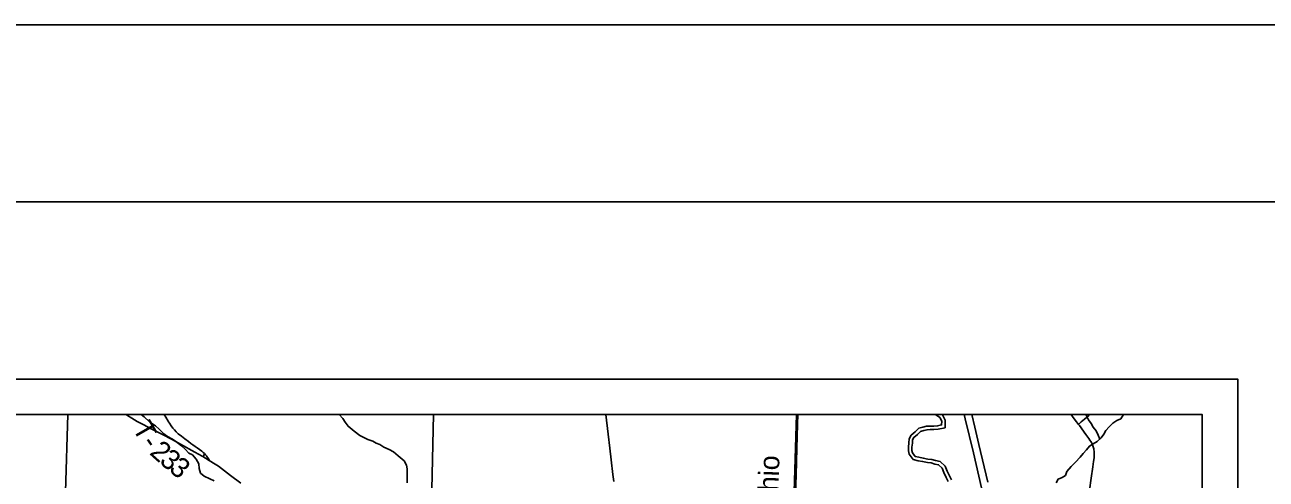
# Model space of a CAD drawing. Extents: x 0 to 34, y 0 to 22.
# Drawn here: x 26.994 to 30.497, y 20.718 to 22 of the extents above; entities that cross this region are included whole.
import ezdxf

# ---------------------------------------------------------------- set-up
doc = ezdxf.new("R2010")
doc.units = 0
for name, color, linetype in [('GM_X_Corporation', 7, 'Continuous'), ('GM_X_County_Road', 7, 'Continuous'), ('GM_X_Interstate_Route', 7, 'Continuous'), ('GM_X_Major_River', 7, 'Continuous'), ('GM_X_Minor_River', 7, 'Continuous'), ('GM_X_Rail_Line', 7, 'Continuous'), ('GM_X_Rail_Line_Text', 7, 'Continuous'), ('GM_X_State_Route', 7, 'Continuous'), ('GM_X_Township_Road', 7, 'Continuous'), ('GM_X_Township_Road_Text', 7, 'Continuous'), ('SH_Border', 7, 'Continuous'), ('SH_Cut_Line', 7, 'Continuous'), ('SH_Data', 7, 'Continuous')]:
    doc.layers.add(name, color=color, linetype=linetype)

msp = doc.modelspace()

# ---------------------------------------------------------------- linework, layer by layer
at = {"layer": 'GM_X_Corporation'}
for points in [[(26.6535, 14.621), (27.01, 14.6164), (27.046, 14.6155), (27.043, 14.755), (27.052, 15.403), (27.0676, 16.5549), (27.0694, 16.6556), (27.0775, 16.888), (27.0944, 18.0731), (27.1039, 18.5696), (27.1064, 18.6537), (27.3971, 18.6436), (28.3421, 18.6121), (28.7772, 18.6028), (29.0074, 18.5935), (29.6561, 18.5791), (29.6772, 18.5786), (30.101, 18.5701), (30.3167, 18.565), (30.3167, 20.9), (23.5167, 20.9)], [(26.3378, 16.673), (27.0694, 16.6556), (27.0775, 16.888), (27.0944, 18.0731), (27.1039, 18.5696), (27.1064, 18.6537), (27.3971, 18.6436), (28.3421, 18.6121), (28.7772, 18.6028), (29.0074, 18.5935), (29.6561, 18.5791), (29.6772, 18.5786), (30.101, 18.5701), (30.3167, 18.565), (30.3167, 20.9), (25.1014, 20.9)]]:
    msp.add_lwpolyline(points, dxfattribs=at)
for points in [[(27.1148, 20.9), (26.1019, 20.9), (26.0969, 20.7089), (26.1216, 20.708), (27.1086, 20.6823)], [(28.1474, 20.9), (27.1148, 20.9), (27.1086, 20.6823), (27.14, 20.6818), (28.1412, 20.646)], [(29.1717, 20.9), (28.1474, 20.9), (28.1412, 20.646), (28.1583, 20.645), (29.1631, 20.6187)]]:
    msp.add_lwpolyline(points, close=True, dxfattribs=at)
at = {"layer": 'GM_X_County_Road'}
for points in [[(29.9671, 20.8723), (29.9619, 20.8793), (29.9525, 20.8917), (29.9464, 20.9)], [(29.998, 20.6871), (30.0029, 20.7203), (30.0078, 20.7522), (30.0099, 20.7676), (30.0111, 20.778), (30.0116, 20.7854), (30.0116, 20.7916), (30.0112, 20.7971), (30.0108, 20.8004), (30.0103, 20.8031), (30.0097, 20.8062), (30.009, 20.8085), (30.0079, 20.812), (30.0067, 20.815), (30.0056, 20.8176), (30.0037, 20.8211), (30.0018, 20.8242), (29.9994, 20.8278), (29.9965, 20.8323), (29.9882, 20.8439), (29.9697, 20.8688), (29.9671, 20.8723)]]:
    msp.add_lwpolyline(points, dxfattribs=at)
at = {"layer": 'GM_X_Interstate_Route'}
for points in [[(29.7763, 20.3387), (29.7722, 20.3591), (29.7621, 20.4065), (29.7537, 20.4429), (29.7354, 20.5196), (29.7175, 20.5946), (29.694, 20.6937), (29.6706, 20.7916), (29.6477, 20.8877), (29.6447, 20.9)], [(29.7116, 20.709), (29.6862, 20.8153), (29.6744, 20.8649), (29.6661, 20.9)]]:
    msp.add_lwpolyline(points, dxfattribs=at)
at = {"layer": 'GM_X_Major_River'}
for points in [[(29.5999, 20.7112), (29.5942, 20.7225), (29.5872, 20.7365), (29.5826, 20.749), (29.5723, 20.7583), (29.5617, 20.7605), (29.5514, 20.7634), (29.5409, 20.7648), (29.5272, 20.7677), (29.5151, 20.7699), (29.5011, 20.7731), (29.4892, 20.7878), (29.4876, 20.7976), (29.4872, 20.8082), (29.4889, 20.82), (29.4892, 20.8314), (29.4948, 20.8417), (29.5064, 20.8513), (29.5166, 20.8612), (29.5279, 20.8648), (29.5384, 20.8671), (29.5486, 20.8676), (29.5588, 20.8677), (29.5698, 20.8682), (29.5811, 20.8706), (29.5814, 20.8816), (29.5756, 20.8922), (29.5638, 20.9)], [(29.6087, 20.7156), (29.6029, 20.727), (29.5963, 20.7404), (29.591, 20.7546), (29.5769, 20.7674), (29.564, 20.77), (29.5535, 20.7731), (29.5425, 20.7745), (29.5291, 20.7774), (29.5171, 20.7795), (29.5066, 20.7819), (29.4985, 20.7919), (29.4974, 20.7986), (29.497, 20.8077), (29.4988, 20.8191), (29.499, 20.8288), (29.5025, 20.8353), (29.513, 20.8439), (29.5218, 20.8525), (29.5304, 20.8552), (29.5398, 20.8574), (29.5489, 20.8578), (29.5591, 20.8579), (29.571, 20.8584), (29.5907, 20.8626), (29.5913, 20.884), (29.5831, 20.899), (29.5816, 20.9)], [(29.6087, 20.7156), (29.6029, 20.727), (29.5963, 20.7404), (29.591, 20.7546), (29.5769, 20.7674), (29.564, 20.77), (29.5535, 20.7731), (29.5425, 20.7745), (29.5291, 20.7774), (29.5171, 20.7795), (29.5066, 20.7819), (29.4985, 20.7919), (29.4974, 20.7986), (29.497, 20.8077), (29.4988, 20.8191), (29.499, 20.8288), (29.5025, 20.8353), (29.513, 20.8439), (29.5218, 20.8525), (29.5304, 20.8552), (29.5398, 20.8574), (29.5489, 20.8578), (29.5591, 20.8579), (29.571, 20.8584), (29.5907, 20.8626), (29.5913, 20.884), (29.5831, 20.899), (29.5816, 20.9)]]:
    msp.add_lwpolyline(points, dxfattribs=at)
at = {"layer": 'GM_X_Minor_River'}
for points in [[(27.5283, 20.7133), (27.5162, 20.7189), (27.5002, 20.7259), (27.49, 20.7349), (27.4861, 20.7481), (27.4844, 20.7614), (27.4775, 20.7738), (27.4668, 20.7862), (27.4569, 20.791), (27.4463, 20.8019), (27.436, 20.812), (27.4192, 20.8251), (27.4082, 20.8318), (27.396, 20.8378), (27.3858, 20.8456), (27.3732, 20.8584), (27.3629, 20.8685), (27.3458, 20.8793), (27.3302, 20.8935), (27.322, 20.9)], [(28.0723, 20.7077), (28.0726, 20.7233), (28.0724, 20.7471), (28.0708, 20.7574), (28.0642, 20.7694), (28.0471, 20.784), (28.0341, 20.7949), (28.0216, 20.8012), (28.0072, 20.8082), (27.9958, 20.8153), (27.9855, 20.8197), (27.9757, 20.8253), (27.962, 20.8301), (27.9525, 20.8346), (27.9392, 20.8405), (27.9229, 20.8528), (27.9061, 20.867), (27.8977, 20.8783), (27.8908, 20.8885), (27.8812, 20.9)], [(29.9039, 20.7076), (29.9095, 20.7179), (29.9208, 20.7222), (29.9309, 20.7283), (29.9342, 20.7394), (29.9466, 20.7531), (29.959, 20.7654), (29.9717, 20.7795), (29.9803, 20.7906), (29.99, 20.8006), (29.9979, 20.8109), (30.0088, 20.8175), (30.0201, 20.8236), (30.0309, 20.834), (30.0384, 20.8451), (30.0443, 20.8546), (30.0537, 20.8657), (30.0642, 20.876), (30.0758, 20.8834), (30.0864, 20.8884), (30.0943, 20.9)], [(30.0272, 20.8304), (30.0225, 20.8422), (30.0175, 20.8539), (30.0087, 20.8641), (30.0026, 20.875), (29.9957, 20.8848), (29.9891, 20.8984), (29.9882, 20.9)]]:
    msp.add_lwpolyline(points, dxfattribs=at)
at = {"layer": 'GM_X_Rail_Line'}
msp.add_lwpolyline([(29.1612, 20.4958), (29.1627, 20.5169), (29.1641, 20.5448), (29.1668, 20.6257), (29.1702, 20.729), (29.1721, 20.8052), (29.1745, 20.8724), (29.1754, 20.9)], dxfattribs=at)
at = {"layer": 'GM_X_State_Route'}
for points in [[(27.2794, 20.9), (27.2837, 20.8971), (27.2957, 20.8895), (27.3108, 20.8808), (27.3292, 20.8706), (27.3463, 20.8617), (27.3823, 20.8435), (27.4076, 20.8302), (27.4333, 20.8164), (27.4736, 20.7942), (27.4942, 20.7827), (27.4962, 20.7815), (27.5143, 20.7708), (27.5309, 20.7605), (27.5402, 20.7542), (27.5488, 20.748), (27.5577, 20.7412), (27.5744, 20.7283), (27.6032, 20.7066)], [(28.6557, 20.7108), (28.6534, 20.7305), (28.6484, 20.7724), (28.6444, 20.8051), (28.6398, 20.8446), (28.6333, 20.9)]]:
    msp.add_lwpolyline(points, dxfattribs=at)
at = {"layer": 'GM_X_Township_Road'}
for points in [[(27.501, 20.79), (27.4974, 20.7934), (27.4932, 20.7968), (27.4868, 20.8014), (27.4803, 20.8061), (27.4742, 20.8103), (27.4682, 20.8147), (27.4627, 20.8187), (27.4557, 20.8239), (27.4453, 20.8316), (27.4355, 20.8391), (27.4269, 20.8461), (27.421, 20.8515), (27.4163, 20.8565), (27.4115, 20.8621), (27.4071, 20.8681), (27.4016, 20.8762), (27.3997, 20.8792), (27.3984, 20.8813), (27.3914, 20.8929), (27.3873, 20.9)], [(29.9671, 20.8723), (29.9703, 20.8752), (29.975, 20.8793), (29.9844, 20.8873), (29.9968, 20.8977), (29.9994, 20.9)], [(27.4962, 20.7815), (27.4979, 20.7829), (27.4991, 20.7848), (27.5001, 20.7871), (27.5007, 20.7886), (27.501, 20.79)], [(27.5143, 20.7708), (27.5139, 20.7718), (27.5136, 20.7725), (27.5129, 20.7738), (27.512, 20.7754), (27.5078, 20.7816), (27.5065, 20.7835), (27.5056, 20.7845), (27.504, 20.7865), (27.501, 20.79)]]:
    msp.add_lwpolyline(points, dxfattribs=at)
at = {"layer": 'SH_Border'}
msp.add_lwpolyline([(1.5, 21.5), (33.5, 21.5), (33.5, 0.5), (1.5, 0.5)], close=True, dxfattribs=at)
at = {"layer": 'SH_Cut_Line'}
msp.add_lwpolyline([(0, 0), (34, 0), (34, 22), (0, 22)], close=True, dxfattribs=at)
at = {"layer": 'SH_Data'}
for points in [[(23.4167, 21), (30.4167, 21), (30.4167, 14), (23.4167, 14)], [(23.5167, 20.9), (30.3167, 20.9), (30.3167, 14.1), (23.5167, 14.1)]]:
    msp.add_lwpolyline(points, close=True, dxfattribs=at)

# ---------------------------------------------------------------- texts
at = {"layer": 'GM_X_Rail_Line_Text'}
msp.add_text('Ohio', height=0.05663, rotation=88.2023, dxfattribs=at).set_placement((29.1185, 20.6242))
at = {"layer": 'GM_X_Township_Road_Text'}
for s, rotation, p in [('T', 299.7789, (27.2966, 20.8611)), ('-', 304.6943, (27.3206, 20.8198)), ('2', 318.2033, (27.3435, 20.7897)), ('3', 319.7851, (27.3709, 20.7652)), ('3', 319.8287, (27.3977, 20.7426))]:
    msp.add_text(s, height=0.0568, rotation=rotation, dxfattribs=at).set_placement(p)

doc.saveas('drawing.dxf')
